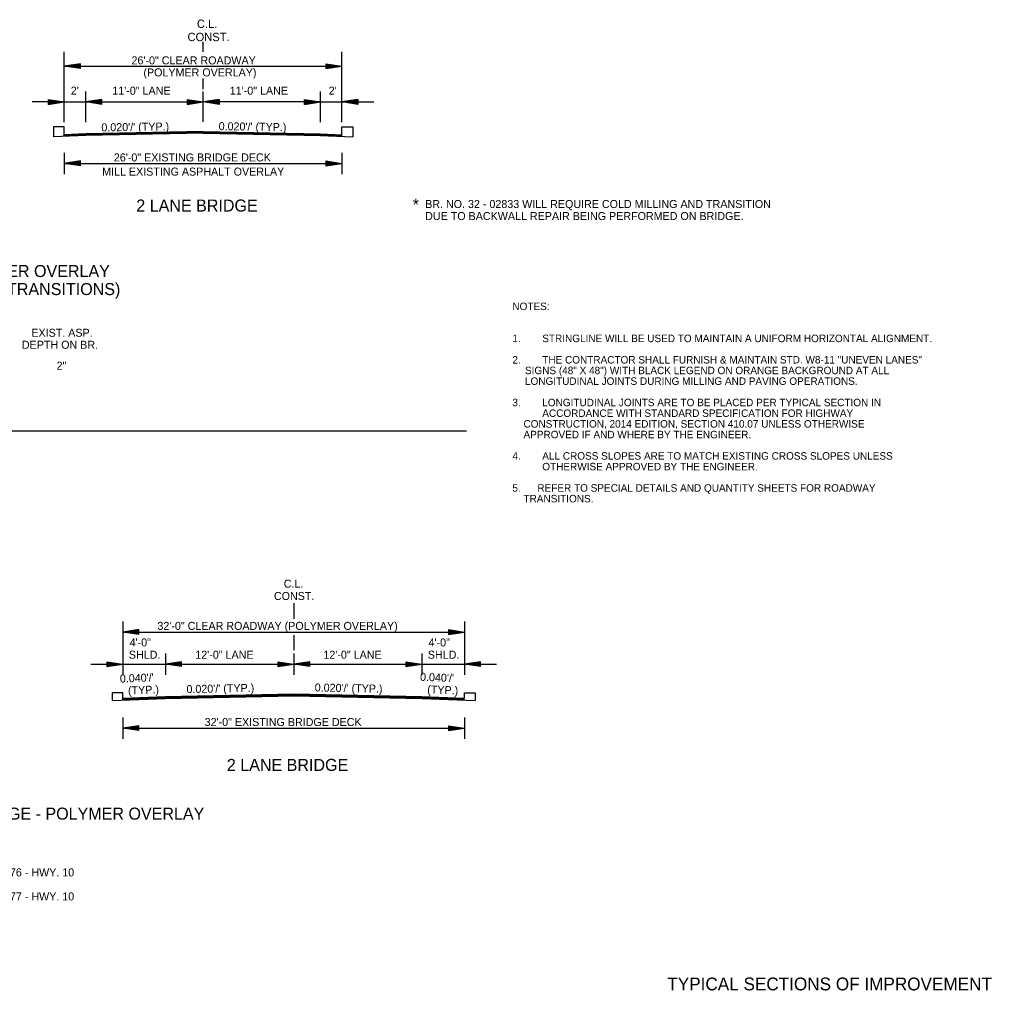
# Model space of a CAD drawing. Extents: x 550980 to 1930787, y -1972975 to 596640.
# Drawn here: x 551635 to 552546, y -1960432 to -1959523 of the extents above; entities that cross this region are included whole.
import ezdxf

# ---------------------------------------------------------------- set-up
doc = ezdxf.new("R2010")
doc.units = 0
for name, color, linetype in [('R_Border', 7, 'Continuous'), ('R_Border Notes', 7, 'Continuous'), ('R_Draft', 7, 'Continuous')]:
    doc.layers.add(name, color=color, linetype=linetype)

# ---------------------------------------------------------------- blocks, each defined once
blk = doc.blocks.new('ARROW')
at = {"layer": 'R_Draft'}
for p, q in [((-2, 0.3), (0, 0)), ((-2, 0.3), (-2, -0.3)), ((-2, 0.25), (-0.334, 0)), ((-2, 0.199), (-0.678, 0)), ((-2, 0.149), (-1.011, 0)), ((-2, 0.097), (-1.35, 0)), ((-2, 0.047), (-1.684, 0)), ((-2, -0.3), (0, 0)), ((-2, -0.098), (-1.35, 0)), ((-2, -0.199), (-0.678, 0)), ((-2, -0.25), (-0.334, 0)), ((-2, -0.149), (-1.011, 0)), ((-2, -0.047), (-1.684, 0))]:
    blk.add_line(p, q, dxfattribs=at)

msp = doc.modelspace()

# ---------------------------------------------------------------- linework, layer by layer
at = {"layer": 'R_Border'}
for p, q in [((551937.52, -1959600.53), (551967.52, -1959600.53)), ((551667.35, -1959623.83), (551667.34, -1959633.21)), ((551677.52, -1959623.83), (551667.35, -1959623.83)), ((551677.52, -1959632.63), (551677.52, -1959623.83)), ((551937.52, -1959632.63), (551937.52, -1959623.83)), ((551937.52, -1959623.83), (551947.69, -1959623.83)), ((551947.69, -1959623.83), (551947.7, -1959633.21)), ((550992.91, -1959908.21), (552054.18, -1959908.21)), ((551892.36, -1960069.68), (551892.36, -1960084.18)), ((551732.36, -1960086.68), (551732.36, -1960136.68)), ((552052.36, -1960086.68), (552052.36, -1960136.68)), ((551732.36, -1960096.68), (552052.36, -1960096.68)), ((551892.36, -1960099.68), (551892.36, -1960113.68)), ((551772.36, -1960116.68), (551772.36, -1960136.68)), ((551892.36, -1960116.68), (551892.36, -1960136.68)), ((552012.36, -1960116.68), (552012.36, -1960136.68)), ((551702.36, -1960126.68), (552082.36, -1960126.68)), ((551732.36, -1960176.68), (551732.36, -1960196.68)), ((552052.36, -1960176.68), (552052.36, -1960196.68)), ((551732.36, -1960186.68), (552052.36, -1960186.68))]:
    msp.add_line(p, q, dxfattribs=at)
for points in [[(551732.36, -1960160.18), (551732.36, -1960153.68), (551722.36, -1960153.68), (551722.36, -1960160.88)], [(551722.36, -1960160.88), (551772.36, -1960158.88), (551892.36, -1960156.48), (552012.36, -1960158.88), (552062.36, -1960160.88)], [(551732.36, -1960158.68), (551772.36, -1960157.08), (551892.36, -1960154.68), (552012.36, -1960157.08), (552052.36, -1960158.68)], [(551732.36, -1960158.98), (551772.36, -1960157.38), (551892.36, -1960154.98), (552012.36, -1960157.38), (552052.36, -1960158.98)], [(551732.36, -1960159.28), (551772.36, -1960157.68), (551892.36, -1960155.28), (552012.36, -1960157.68), (552052.36, -1960159.28)], [(551732.36, -1960159.58), (551772.36, -1960157.98), (551892.36, -1960155.58), (552012.36, -1960157.98), (552052.36, -1960159.58)], [(551732.36, -1960159.88), (551772.36, -1960158.28), (551892.36, -1960155.88), (552012.36, -1960158.28), (552052.36, -1960159.88)], [(551732.36, -1960160.18), (551772.36, -1960158.58), (551892.36, -1960156.18), (552012.36, -1960158.58), (552052.36, -1960160.18)], [(552052.36, -1960158.68), (552052.36, -1960153.68), (552062.36, -1960153.68), (552062.36, -1960160.88)]]:
    msp.add_lwpolyline(points, dxfattribs=at)
at = {"layer": 'R_Draft'}
for p, q in [((551807.52, -1959553.57), (551807.52, -1959544.27)), ((551677.52, -1959619.35), (551677.52, -1959553.62)), ((551937.52, -1959619.35), (551937.52, -1959553.62)), ((551692.52, -1959564.74), (551677.52, -1959566.99)), ((551677.52, -1959566.99), (551935.52, -1959566.99)), ((551692.52, -1959569.24), (551677.52, -1959566.99)), ((551692.52, -1959565.11), (551680.02, -1959566.99)), ((551692.52, -1959568.86), (551680.02, -1959566.99)), ((551692.52, -1959565.5), (551682.6, -1959566.99)), ((551692.52, -1959568.48), (551682.6, -1959566.99)), ((551692.52, -1959565.87), (551685.1, -1959566.99)), ((551692.52, -1959568.11), (551685.1, -1959566.99)), ((551692.52, -1959566.25), (551687.64, -1959566.99)), ((551692.52, -1959567.72), (551687.64, -1959566.99)), ((551692.52, -1959566.64), (551690.15, -1959566.99)), ((551692.52, -1959567.34), (551690.15, -1959566.99)), ((551692.52, -1959569.24), (551692.52, -1959564.74)), ((551922.52, -1959564.74), (551937.52, -1959566.99)), ((551922.52, -1959564.74), (551922.52, -1959569.24)), ((551922.52, -1959565.11), (551935.01, -1959566.99)), ((551922.52, -1959565.5), (551932.43, -1959566.99)), ((551922.52, -1959565.87), (551929.94, -1959566.99)), ((551922.52, -1959566.26), (551927.39, -1959566.99)), ((551922.52, -1959566.64), (551924.89, -1959566.99)), ((551922.52, -1959569.24), (551937.52, -1959566.99)), ((551922.52, -1959567.72), (551927.39, -1959566.99)), ((551922.52, -1959568.48), (551932.43, -1959566.99)), ((551922.52, -1959568.86), (551935.01, -1959566.99)), ((551922.52, -1959568.11), (551929.94, -1959566.99)), ((551922.52, -1959567.34), (551924.89, -1959566.99)), ((551807.52, -1959588.51), (551807.52, -1959578.64)), ((551697.52, -1959619.35), (551697.52, -1959590.63)), ((551807.52, -1959619.18), (551807.52, -1959590.63)), ((551917.52, -1959619.35), (551917.52, -1959590.63)), ((551677.52, -1959600.53), (551647.52, -1959600.53)), ((551662.52, -1959598.28), (551677.52, -1959600.53)), ((551662.52, -1959598.28), (551662.52, -1959602.78)), ((551662.52, -1959598.65), (551675.01, -1959600.53)), ((551662.52, -1959599.03), (551672.43, -1959600.53)), ((551662.52, -1959599.41), (551669.94, -1959600.53)), ((551662.52, -1959599.8), (551667.39, -1959600.53)), ((551662.52, -1959600.17), (551664.89, -1959600.53)), ((551662.52, -1959602.78), (551677.52, -1959600.53)), ((551662.52, -1959601.26), (551667.39, -1959600.53)), ((551662.52, -1959602.02), (551672.43, -1959600.53)), ((551662.52, -1959602.4), (551675.01, -1959600.53)), ((551662.52, -1959601.64), (551669.94, -1959600.53)), ((551662.52, -1959600.88), (551664.89, -1959600.53)), ((551677.52, -1959600.53), (551697.52, -1959600.53)), ((551712.52, -1959598.28), (551697.52, -1959600.53)), ((551712.52, -1959602.78), (551697.52, -1959600.53)), ((551697.52, -1959600.53), (551807.52, -1959600.53)), ((551712.52, -1959598.65), (551700.02, -1959600.53)), ((551712.52, -1959602.4), (551700.02, -1959600.53)), ((551712.52, -1959599.03), (551702.6, -1959600.53)), ((551712.52, -1959602.02), (551702.6, -1959600.53)), ((551712.52, -1959599.41), (551705.1, -1959600.53)), ((551712.52, -1959601.64), (551705.1, -1959600.53)), ((551712.52, -1959599.79), (551707.64, -1959600.53)), ((551712.52, -1959601.25), (551707.64, -1959600.53)), ((551712.52, -1959600.17), (551710.15, -1959600.53)), ((551712.52, -1959600.88), (551710.15, -1959600.53)), ((551712.52, -1959602.78), (551712.52, -1959598.28)), ((551792.52, -1959598.28), (551807.52, -1959600.53)), ((551792.52, -1959598.28), (551792.52, -1959602.78)), ((551792.52, -1959598.65), (551805.01, -1959600.53)), ((551792.52, -1959599.03), (551802.43, -1959600.53)), ((551792.52, -1959599.41), (551799.94, -1959600.53)), ((551792.52, -1959599.8), (551797.39, -1959600.53)), ((551792.52, -1959600.17), (551794.89, -1959600.53)), ((551792.52, -1959602.78), (551807.52, -1959600.53)), ((551792.52, -1959601.26), (551797.39, -1959600.53)), ((551792.52, -1959602.02), (551802.43, -1959600.53)), ((551792.52, -1959602.4), (551805.01, -1959600.53)), ((551792.52, -1959601.64), (551799.94, -1959600.53)), ((551792.52, -1959600.88), (551794.89, -1959600.53)), ((551822.52, -1959598.28), (551807.52, -1959600.53)), ((551917.52, -1959600.53), (551807.52, -1959600.53)), ((551822.52, -1959602.78), (551807.52, -1959600.53)), ((551822.52, -1959598.65), (551810.02, -1959600.53)), ((551822.52, -1959602.4), (551810.02, -1959600.53)), ((551822.52, -1959599.03), (551812.6, -1959600.53)), ((551822.52, -1959602.02), (551812.6, -1959600.53)), ((551822.52, -1959599.41), (551815.1, -1959600.53)), ((551822.52, -1959601.64), (551815.1, -1959600.53)), ((551822.52, -1959599.8), (551817.64, -1959600.53)), ((551822.52, -1959601.26), (551817.64, -1959600.53)), ((551822.52, -1959600.17), (551820.15, -1959600.53)), ((551822.52, -1959600.88), (551820.15, -1959600.53)), ((551822.52, -1959598.28), (551822.52, -1959602.78)), ((551902.52, -1959598.28), (551917.52, -1959600.53)), ((551902.52, -1959602.78), (551902.52, -1959598.28)), ((551902.52, -1959598.65), (551915.01, -1959600.53)), ((551902.52, -1959599.03), (551912.43, -1959600.53)), ((551902.52, -1959599.41), (551909.94, -1959600.53)), ((551902.52, -1959599.79), (551907.39, -1959600.53)), ((551902.52, -1959600.17), (551904.89, -1959600.53)), ((551902.52, -1959602.78), (551917.52, -1959600.53)), ((551902.52, -1959601.25), (551907.39, -1959600.53)), ((551902.52, -1959602.02), (551912.43, -1959600.53)), ((551902.52, -1959602.4), (551915.01, -1959600.53)), ((551902.52, -1959601.64), (551909.94, -1959600.53)), ((551902.52, -1959600.88), (551904.89, -1959600.53)), ((551917.52, -1959600.53), (551937.52, -1959600.53)), ((551952.52, -1959598.28), (551937.52, -1959600.53)), ((551952.52, -1959602.78), (551937.52, -1959600.53)), ((551952.52, -1959598.65), (551940.02, -1959600.53)), ((551952.52, -1959602.4), (551940.02, -1959600.53)), ((551952.52, -1959599.03), (551942.6, -1959600.53)), ((551952.52, -1959602.02), (551942.6, -1959600.53)), ((551952.52, -1959599.41), (551945.1, -1959600.53)), ((551952.52, -1959601.64), (551945.1, -1959600.53)), ((551952.52, -1959599.8), (551947.64, -1959600.53)), ((551952.52, -1959601.26), (551947.64, -1959600.53)), ((551952.52, -1959600.17), (551950.15, -1959600.53)), ((551952.52, -1959600.88), (551950.15, -1959600.53)), ((551952.52, -1959598.28), (551952.52, -1959602.78)), ((551697.52, -1959632), (551667.34, -1959633.21)), ((551697.52, -1959630.33), (551677.52, -1959631.13)), ((551697.52, -1959630.63), (551677.52, -1959631.43)), ((551697.52, -1959630.93), (551677.52, -1959631.73)), ((551697.52, -1959631.23), (551677.52, -1959632.03)), ((551697.52, -1959631.53), (551677.52, -1959632.33)), ((551697.52, -1959631.83), (551677.52, -1959632.63)), ((551807.52, -1959628.13), (551697.52, -1959630.33)), ((551807.52, -1959628.43), (551697.52, -1959630.63)), ((551807.53, -1959628.73), (551697.52, -1959630.93)), ((551807.54, -1959629.03), (551697.52, -1959631.23)), ((551807.54, -1959629.33), (551697.52, -1959631.53)), ((551807.55, -1959629.63), (551697.52, -1959631.83)), ((551807.55, -1959629.8), (551697.52, -1959632)), ((551807.48, -1959629.8), (551917.52, -1959632)), ((551807.49, -1959629.33), (551917.52, -1959631.53)), ((551807.49, -1959629.63), (551917.52, -1959631.83)), ((551807.5, -1959629.03), (551917.52, -1959631.23)), ((551807.51, -1959628.43), (551917.52, -1959630.63)), ((551807.51, -1959628.73), (551917.52, -1959630.93)), ((551807.52, -1959628.13), (551917.52, -1959630.33)), ((551917.52, -1959630.33), (551937.52, -1959631.13)), ((551917.52, -1959630.63), (551937.52, -1959631.43)), ((551917.52, -1959630.93), (551937.52, -1959631.73)), ((551917.52, -1959631.23), (551937.52, -1959632.03)), ((551917.52, -1959631.53), (551937.52, -1959632.33)), ((551917.52, -1959631.83), (551937.52, -1959632.63)), ((551917.52, -1959632), (551947.7, -1959633.21)), ((551677.52, -1959647.99), (551677.52, -1959667.99)), ((551937.52, -1959647.99), (551937.52, -1959667.99)), ((551692.52, -1959655.74), (551677.52, -1959657.99)), ((551677.52, -1959657.99), (551937.52, -1959657.99)), ((551692.52, -1959660.24), (551677.52, -1959657.99)), ((551692.52, -1959656.12), (551680.02, -1959657.99)), ((551692.52, -1959659.87), (551680.02, -1959657.99)), ((551692.52, -1959656.5), (551682.6, -1959657.99)), ((551692.52, -1959659.48), (551682.6, -1959657.99)), ((551692.52, -1959656.87), (551685.1, -1959657.99)), ((551692.52, -1959659.11), (551685.1, -1959657.99)), ((551692.52, -1959657.26), (551687.64, -1959657.99)), ((551692.52, -1959658.72), (551687.64, -1959657.99)), ((551692.52, -1959657.64), (551690.15, -1959657.99)), ((551692.52, -1959658.34), (551690.15, -1959657.99)), ((551692.52, -1959660.24), (551692.52, -1959655.74)), ((551922.52, -1959655.74), (551937.52, -1959657.99)), ((551922.52, -1959655.74), (551922.52, -1959660.24)), ((551922.52, -1959656.12), (551935.01, -1959657.99)), ((551922.52, -1959656.5), (551932.43, -1959657.99)), ((551922.52, -1959656.87), (551929.94, -1959657.99)), ((551922.52, -1959657.26), (551927.39, -1959657.99)), ((551922.52, -1959657.64), (551924.89, -1959657.99)), ((551922.52, -1959660.24), (551937.52, -1959657.99)), ((551922.52, -1959658.73), (551927.39, -1959657.99)), ((551922.52, -1959659.48), (551932.43, -1959657.99)), ((551922.52, -1959659.87), (551935.01, -1959657.99)), ((551922.52, -1959659.11), (551929.94, -1959657.99)), ((551922.52, -1959658.34), (551924.89, -1959657.99))]:
    msp.add_line(p, q, dxfattribs=at)

# ---------------------------------------------------------------- block references
at = {"layer": 'R_Border', "xscale": 7.5, "yscale": 7.5, "rotation": 180}
for p in [(551732.36, -1960096.68), (551772.36, -1960126.68), (551892.36, -1960126.68), (552052.36, -1960126.68), (551732.36, -1960186.68)]:
    msp.add_blockref('ARROW', p, dxfattribs=at)
at = {"layer": 'R_Border', "xscale": 7.5, "yscale": 7.5}
for p in [(552052.36, -1960096.68), (551732.36, -1960126.68), (551892.36, -1960126.68), (552012.36, -1960126.68), (552052.36, -1960186.68)]:
    msp.add_blockref('ARROW', p, dxfattribs=at)

# ---------------------------------------------------------------- texts
at = {"layer": 'R_Border'}
for s, height, p in [('EXIST. ASP.', 7.5, (551646.63, -1959820.29)), ('DEPTH ON BR.', 7.5, (551637.77, -1959831.54)), ('C.L.', 7.5, (551883.03, -1960055.18)), ('CONST.', 7.5, (551873.82, -1960066.68)), ('32\'-0" CLEAR ROADWAY (POLYMER OVERLAY)', 7.5, (551764.69, -1960094.68)), ('4\'-0"', 7.5, (551738.63, -1960110.18)), ('4\'-0"', 7.5, (552018.63, -1960110.18)), ('SHLD.', 7.5, (551737.95, -1960121.68)), ('12\'-0" LANE', 7.5, (551800.18, -1960121.68)), ('12\'-0" LANE', 7.5, (551920.18, -1960121.68)), ('SHLD.', 7.5, (552017.95, -1960121.68)), ('32\'-0" EXISTING BRIDGE DECK', 7.5, (551808.92, -1960184.68)), ('2 LANE BRIDGE', 11.25, (551829.74, -1960226.68)), ('32 FT. CLEAR ROADWAY BRIDGE - POLYMER OVERLAY', 11.25, (551404.88, -1960272.3)), ('- BR NO. 06676 - HWY. 10', 7.5, (551566.36, -1960325.43)), ('- BR NO. 06677 - HWY. 10', 7.5, (551566.36, -1960347.95))]:
    msp.add_text(s, height=height, dxfattribs=at).set_placement(p)
for s, height, rotation, p in [("0.040'/'", 7.5, 2.2916, (551729.66, -1960144.08)), ("0.040'/'", 7.5, 357.7084, (552010.58, -1960142.29)), ('(TYP.)', 7.5, 2.2916, (551737.32, -1960155.28)), ("0.020'/' (TYP.)", 7.5, 1.1458, (551791.98, -1960153.88)), ("0.020'/' (TYP.)", 7.5, 358.8542, (551911.98, -1960152.27)), ('(TYP.)', 7.5, 357.7084, (552017.32, -1960154.07)), ('TYPICAL SECTIONS OF IMPROVEMENT', 12, 360, (552242.27, -1960432.11))]:
    msp.add_text(s, height=height, rotation=rotation, dxfattribs=at).set_placement(p)
at = {"layer": 'R_Border Notes'}
for s, p in [('NOTES: ', (552097.15, -1959795.32)), ('1.', (552097.15, -1959825.32)), ('STRINGLINE WILL BE USED TO MAINTAIN A UNIFORM HORIZONTAL ALIGNMENT.', (552125.15, -1959825.32)), ('2.', (552097.15, -1959845.32)), ('THE CONTRACTOR SHALL FURNISH & MAINTAIN STD. W8-11 "UNEVEN LANES" ', (552125.15, -1959845.32)), ('    SIGNS (48" X 48") WITH BLACK LEGEND ON ORANGE BACKGROUND AT ALL ', (552098.55, -1959855.32)), ('    LONGITUDINAL JOINTS DURING MILLING AND PAVING OPERATIONS.', (552098.55, -1959865.32)), ('3.', (552097.15, -1959885.32)), ('LONGITUDINAL JOINTS ARE TO BE PLACED PER TYPICAL SECTION IN ', (552125.15, -1959885.32)), ('ACCORDANCE WITH STANDARD SPECIFICATION FOR HIGHWAY', (552125.15, -1959895.32)), ('    CONSTRUCTION, 2014 EDITION, SECTION 410.07 UNLESS OTHERWISE', (552097.15, -1959905.32)), ('    APPROVED IF AND WHERE BY THE ENGINEER.', (552097.15, -1959915.32)), ('4.', (552097.15, -1959935.32)), ('ALL CROSS SLOPES ARE TO MATCH EXISTING CROSS SLOPES UNLESS ', (552125.15, -1959935.32)), ('OTHERWISE APPROVED BY THE ENGINEER.', (552125.15, -1959945.32)), ('5.      REFER TO SPECIAL DETAILS AND QUANTITY SHEETS FOR ROADWAY', (552097.15, -1959965.32)), ('    TRANSITIONS.', (552097.15, -1959975.32))]:
    msp.add_text(s, height=7, dxfattribs=at).set_placement(p)
at = {"layer": 'R_Draft'}
for s, height, p in [('C.L.', 7.8, (551801.67, -1959531.18)), ('CONST.', 7.8, (551792.89, -1959543.54)), ('26\'-0" CLEAR ROADWAY ', 7.5, (551740.43, -1959565.32)), ('(POLYMER OVERLAY)', 7.5, (551751.59, -1959576.57)), ("2'", 7.5, (551683.56, -1959593.66)), ('11\'-0" LANE', 7.5, (551722.46, -1959593.66)), ('11\'-0" LANE', 7.5, (551832.46, -1959593.66)), ("2'", 7.5, (551925.12, -1959593.66)), ('26\'-0" EXISTING BRIDGE DECK', 7.5, (551723.9, -1959656.16)), ('MILL EXISTING ASPHALT OVERLAY', 7.5, (551712.94, -1959669.43)), ('2 LANE BRIDGE', 11.25, (551744.92, -1959703.07)), ('*', 11.25, (552003.83, -1959702.15)), ('BR. NO. 32 - 02833 WILL REQUIRE COLD MILLING AND TRANSITION', 7.5, (552015.48, -1959699.78)), ('DUE TO BACKWALL REPAIR BEING PERFORMED ON BRIDGE.', 7.5, (552015.48, -1959711.03)), ('26 FT. CLEAR ROADWAY BRIDGE - POLYMER OVERLAY', 11.25, (551316.41, -1959764.39)), ('(MILL ASPHALT ON BR. DECK, ROADWAY TRANSITIONS)', 11.25, (551320.4, -1959781.27)), ('2"', 7.5, (551670.26, -1959851.14))]:
    msp.add_text(s, height=height, dxfattribs=at).set_placement(p)
for rotation, p in [(0.87191, (551712.26, -1959628.09)), (359.12809, (551822.01, -1959626.86))]:
    msp.add_text("0.020'/' (TYP.)", height=7.5, rotation=rotation, dxfattribs=at).set_placement(p)

doc.saveas('drawing.dxf')
